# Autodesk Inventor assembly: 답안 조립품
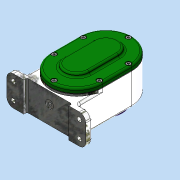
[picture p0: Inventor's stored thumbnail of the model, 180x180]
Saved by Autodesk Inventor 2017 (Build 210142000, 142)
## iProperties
Part Number: 답안 조립품
Material: 일반
Document SubType Name: Assembly
Designer: MRC
Author: MRC
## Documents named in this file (19)
- C:\Users\MRC\Desktop\710609V1015\답안 조립품.iam
- C:\Users\MRC\Desktop\710609V1015\본체.ipt
- C:\Users\MRC\Desktop\710609V1015\개스킷 A.ipt
- C:\Users\MRC\Desktop\710609V1015\개스킷 B.ipt
- C:\Users\MRC\Desktop\710609V1015\베어링 6001.ipt
- 베어링 6001.ipt
- C:\Users\MRC\Desktop\710609V1015\베어링 6002.ipt
- 베어링 6002.ipt
- C:\Users\MRC\Desktop\710609V1015\볼트 M4.ipt
- C:\Users\MRC\Desktop\710609V1015\스퍼기어 A.ipt
- C:\Users\MRC\Desktop\710609V1015\스퍼기어 B.ipt
- C:\Users\MRC\Desktop\710609V1015\오일 실 12 22 7.ipt
- C:\Users\MRC\Desktop\710609V1015\축 A.ipt
- C:\Users\MRC\Desktop\710609V1015\축 B.ipt
- C:\Users\MRC\Desktop\710609V1015\칼라.ipt
- C:\Users\MRC\Desktop\710609V1015\커버 A.ipt
- C:\Users\MRC\Desktop\710609V1015\커버 B.ipt
- C:\Users\MRC\Desktop\710609V1015\키 4 x 4 x 12.ipt
- C:\Users\MRC\Desktop\710609V1015\키 5 x 5 x 12.ipt
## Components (2 placed, 2 different names)
1. 개스킷 A:1
2. 개스킷 B:1
